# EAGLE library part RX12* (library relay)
SMALL MICRO WAVE RELAY NAiS Source: http://www.mew-europe.com/.. en_ds_61307_0000.pdf
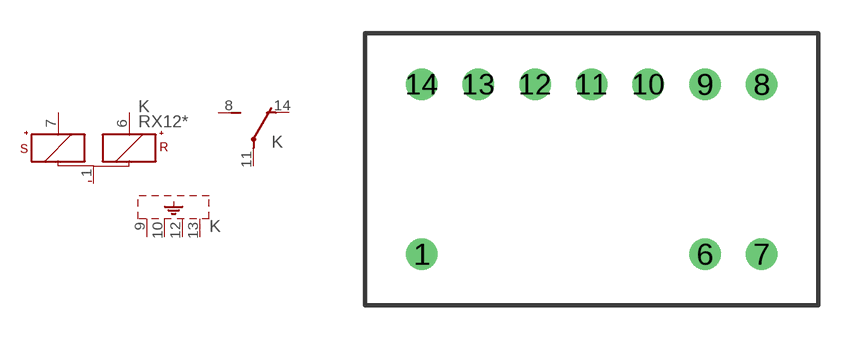
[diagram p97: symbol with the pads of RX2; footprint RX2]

Designator prefix K; gates 1=+KS+KR- 2=U 3=SHIELD-4

## RX12 (OC_FARNELL: unknown; OC_NEWARK: unknown)  [RX2]
1  1:-  pas
6  1:R+  pas
7  1:S+  pas
8  2:S  pas
9  3:SH  pas
10  3:SH  pas
11  2:P  pas
12  3:SH  pas
13  3:SH  pas
14  2:O  pas

## Footprint RX2 (pad centres in mm)
SMALL MICRO WAVE RELAY NAiS Source: http://www.mew-europe.com/.. en_ds_61307_0000.pdf
drill 0.9 round: 1 -7.62,-3.81; 6 5.08,-3.81; 7 7.62,-3.81; 8 7.62,3.81; 9 5.08,3.81; 10 2.54,3.81; 11 0,3.81; 12 -2.54,3.81; 13 -5.08,3.81; 14 -7.62,3.81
